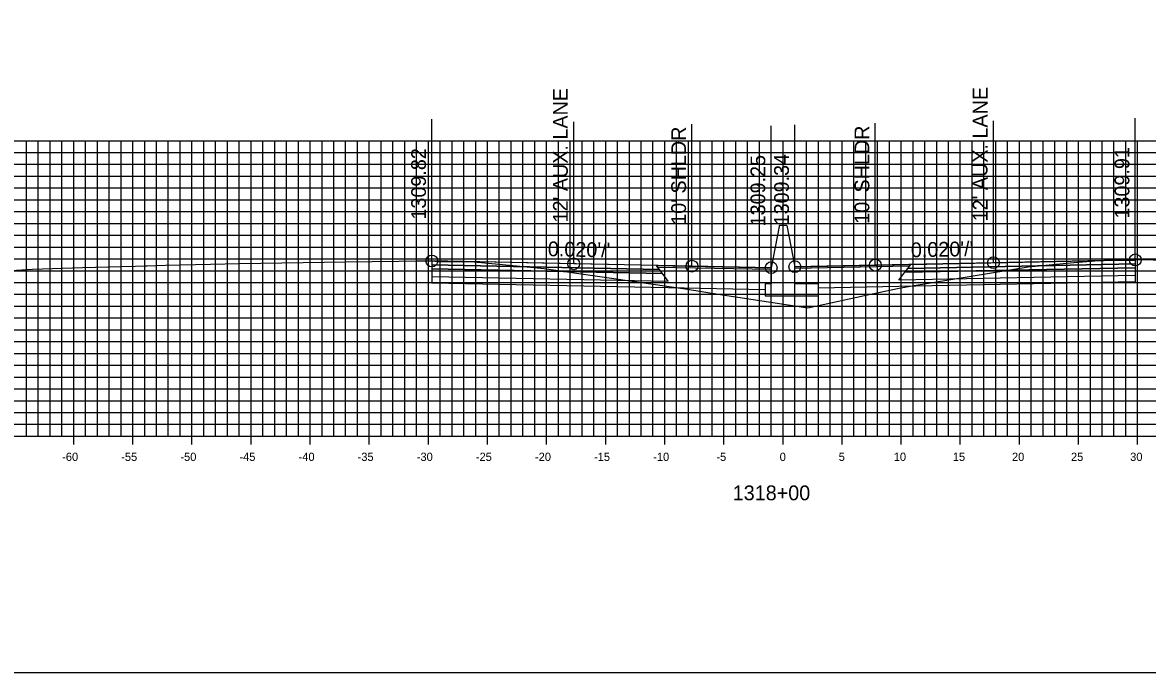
# Model space of a CAD drawing. Extents: x 674939 to 678919, y 750652 to 765176.
# Drawn here: x 678674.2 to 678769.4, y 751152.6 to 751207.6 of the extents above; entities that cross this region are included whole.
import ezdxf

# ---------------------------------------------------------------- set-up
doc = ezdxf.new("R2010")
doc.units = 0
for name, color, linetype in [('Level 10', 7, 'Continuous'), ('Level 17', 7, 'Continuous'), ('Level 18', 7, 'Continuous'), ('Level 19', 7, 'Continuous'), ('Level 20', 7, 'Continuous'), ('Level 22', 7, 'Continuous'), ('Level 23', 7, 'Continuous'), ('Level 4', 7, 'Continuous'), ('Level 8', 7, 'Continuous'), ('Level 9', 7, 'Continuous')]:
    doc.layers.add(name, color=color, linetype=linetype)

msp = doc.modelspace()

# ---------------------------------------------------------------- linework, layer by layer
at = {"layer": 'Level 10'}
msp.add_lwpolyline([(678672.798, 751186.531), (678675.035, 751186.674), (678679.285, 751186.811), (678682.538, 751186.906), (678683.76, 751186.937), (678684.6, 751186.959), (678684.754, 751186.963), (678686.303, 751187.004), (678690.088, 751187.095), (678692.56, 751187.145), (678701.524, 751187.286), (678706.033, 751187.361), (678707.563, 751187.382), (678708.483, 751187.391), (678708.729, 751187.38), (678708.827, 751187.374), (678709.304, 751187.338), (678709.738, 751187.319), (678710.774, 751187.315), (678711.453, 751187.312), (678711.708, 751187.314), (678712.399, 751187.288), (678712.653, 751187.271), (678712.689, 751187.269), (678712.719, 751187.267), (678715.986, 751186.956), (678718.318, 751186.739), (678727.154, 751185.464), (678730.457, 751184.993), (678733.041, 751184.565), (678740.643, 751183.41), (678746.07, 751184.596), (678748.361, 751185.085), (678749.462, 751185.263), (678759.271, 751186.884), (678762.815, 751187.201), (678764.57, 751187.358), (678764.635, 751187.365), (678765.181, 751187.419), (678765.69, 751187.423), (678766.053, 751187.428), (678766.902, 751187.437), (678768.09, 751187.446), (678768.181, 751187.446), (678768.232, 751187.452), (678768.336, 751187.463), (678768.346, 751187.465), (678768.581, 751187.49), (678774.86, 751187.367)], dxfattribs=at)
at = {"layer": 'Level 17'}
for points in [[(678738.203, 751190.299), (678737.533, 751186.799)], [(678738.863, 751190.387), (678738.863, 751190.387), (678738.203, 751190.387), (678738.203, 751190.299)], [(678738.863, 751190.387), (678739.533, 751186.887)], [(678737.533, 751186.799), (678737.533, 751185.424), (678737.033, 751185.424), (678737.033, 751184.424), (678741.533, 751184.424), (678741.533, 751185.424), (678739.533, 751185.424), (678739.533, 751186.887)]]:
    msp.add_lwpolyline(points, dxfattribs=at)
at = {"layer": 'Level 18'}
for points in [[(678768.336, 751187.463), (678756.336, 751187.223), (678746.336, 751187.023), (678739.533, 751186.887)], [(678737.533, 751186.799), (678730.827, 751186.934), (678720.827, 751187.134), (678708.827, 751187.374)]]:
    msp.add_lwpolyline(points, dxfattribs=at)
for points in [[(678768.336, 751187.463), (678768.336, 751187.133), (678749.086, 751186.748), (678749.336, 751187.083)], [(678708.827, 751187.374), (678708.827, 751187.044), (678728.077, 751186.659), (678727.827, 751186.994)], [(678727.827, 751186.994), (678737.533, 751186.799), (678737.537, 751186.642), (678727.947, 751186.834)], [(678749.217, 751186.924), (678739.533, 751186.73), (678739.533, 751186.887), (678749.336, 751187.083)]]:
    msp.add_lwpolyline(points, close=True, dxfattribs=at)
at = {"layer": 'Level 19'}
for points in [[(678708.827, 751187.044), (678708.827, 751186.714), (678728.327, 751186.324), (678728.077, 751186.659)], [(678708.827, 751186.714), (678708.827, 751186.054), (678728.827, 751185.654), (678728.327, 751186.324)], [(678768.336, 751186.803), (678768.336, 751186.143), (678748.336, 751185.743), (678748.836, 751186.413)], [(678768.336, 751187.133), (678768.336, 751186.803), (678748.836, 751186.413), (678749.086, 751186.748)]]:
    msp.add_lwpolyline(points, close=True, dxfattribs=at)
for points in [[(678708.827, 751186.054), (678708.827, 751185.514), (678728.827, 751185.114), (678737.033, 751184.949)], [(678768.336, 751186.143), (678768.336, 751185.603), (678748.336, 751185.203), (678741.533, 751185.067)]]:
    msp.add_lwpolyline(points, dxfattribs=at)
at = {"layer": 'Level 20'}
for p, q in [((678638.533, 751197.551), (678838.533, 751197.551)), ((678674.533, 751172.551), (678674.533, 751197.551)), ((678675.533, 751172.551), (678675.533, 751197.551)), ((678676.533, 751172.551), (678676.533, 751197.551)), ((678677.533, 751172.551), (678677.533, 751197.551)), ((678678.533, 751172.551), (678678.533, 751197.551)), ((678679.533, 751172.551), (678679.533, 751197.551)), ((678680.533, 751172.551), (678680.533, 751197.551)), ((678681.533, 751172.551), (678681.533, 751197.551)), ((678682.533, 751172.551), (678682.533, 751197.551)), ((678683.533, 751172.551), (678683.533, 751197.551)), ((678684.533, 751172.551), (678684.533, 751197.551)), ((678685.533, 751172.551), (678685.533, 751197.551)), ((678686.533, 751172.551), (678686.533, 751197.551)), ((678687.533, 751172.551), (678687.533, 751197.551)), ((678688.533, 751172.551), (678688.533, 751197.551)), ((678689.533, 751172.551), (678689.533, 751197.551)), ((678690.533, 751172.551), (678690.533, 751197.551)), ((678691.533, 751172.551), (678691.533, 751197.551)), ((678692.533, 751172.551), (678692.533, 751197.551)), ((678693.533, 751172.551), (678693.533, 751197.551)), ((678694.533, 751172.551), (678694.533, 751197.551)), ((678695.533, 751172.551), (678695.533, 751197.551)), ((678696.533, 751172.551), (678696.533, 751197.551)), ((678697.533, 751172.551), (678697.533, 751197.551)), ((678698.533, 751172.551), (678698.533, 751197.551)), ((678699.533, 751172.551), (678699.533, 751197.551)), ((678700.533, 751172.551), (678700.533, 751197.551)), ((678701.533, 751172.551), (678701.533, 751197.551)), ((678702.533, 751172.551), (678702.533, 751197.551)), ((678703.533, 751172.551), (678703.533, 751197.551)), ((678704.533, 751172.551), (678704.533, 751197.551)), ((678705.533, 751172.551), (678705.533, 751197.551)), ((678706.533, 751172.551), (678706.533, 751197.551)), ((678707.533, 751172.551), (678707.533, 751197.551)), ((678708.533, 751172.551), (678708.533, 751197.551)), ((678709.533, 751172.551), (678709.533, 751197.551)), ((678710.533, 751172.551), (678710.533, 751197.551)), ((678711.533, 751172.551), (678711.533, 751197.551)), ((678712.533, 751172.551), (678712.533, 751197.551)), ((678713.533, 751172.551), (678713.533, 751197.551)), ((678714.533, 751172.551), (678714.533, 751197.551)), ((678715.533, 751172.551), (678715.533, 751197.551)), ((678716.533, 751172.551), (678716.533, 751197.551)), ((678717.533, 751172.551), (678717.533, 751197.551)), ((678718.533, 751172.551), (678718.533, 751197.551)), ((678719.533, 751172.551), (678719.533, 751197.551)), ((678720.533, 751172.551), (678720.533, 751197.551)), ((678721.533, 751172.551), (678721.533, 751197.551)), ((678722.533, 751172.551), (678722.533, 751197.551)), ((678723.533, 751172.551), (678723.533, 751197.551)), ((678724.533, 751172.551), (678724.533, 751197.551)), ((678725.533, 751172.551), (678725.533, 751197.551)), ((678726.533, 751172.551), (678726.533, 751197.551)), ((678727.533, 751172.551), (678727.533, 751197.551)), ((678728.533, 751172.551), (678728.533, 751197.551)), ((678729.533, 751172.551), (678729.533, 751197.551)), ((678730.533, 751172.551), (678730.533, 751197.551)), ((678731.533, 751172.551), (678731.533, 751197.551)), ((678732.533, 751172.551), (678732.533, 751197.551)), ((678733.533, 751172.551), (678733.533, 751197.551)), ((678734.533, 751172.551), (678734.533, 751197.551)), ((678735.533, 751172.551), (678735.533, 751197.551)), ((678736.533, 751172.551), (678736.533, 751197.551)), ((678737.533, 751172.551), (678737.533, 751197.551)), ((678738.533, 751172.551), (678738.533, 751197.551)), ((678739.533, 751172.551), (678739.533, 751197.551)), ((678740.533, 751172.551), (678740.533, 751197.551)), ((678741.533, 751172.551), (678741.533, 751197.551)), ((678742.533, 751172.551), (678742.533, 751197.551)), ((678743.533, 751172.551), (678743.533, 751197.551)), ((678744.533, 751172.551), (678744.533, 751197.551)), ((678745.533, 751172.551), (678745.533, 751197.551)), ((678746.533, 751172.551), (678746.533, 751197.551)), ((678747.533, 751172.551), (678747.533, 751197.551)), ((678748.533, 751172.551), (678748.533, 751197.551)), ((678749.533, 751172.551), (678749.533, 751197.551)), ((678750.533, 751172.551), (678750.533, 751197.551)), ((678751.533, 751172.551), (678751.533, 751197.551)), ((678752.533, 751172.551), (678752.533, 751197.551)), ((678753.533, 751172.551), (678753.533, 751197.551)), ((678754.533, 751172.551), (678754.533, 751197.551)), ((678755.533, 751172.551), (678755.533, 751197.551)), ((678756.533, 751172.551), (678756.533, 751197.551)), ((678757.533, 751172.551), (678757.533, 751197.551)), ((678758.533, 751172.551), (678758.533, 751197.551)), ((678759.533, 751172.551), (678759.533, 751197.551)), ((678760.533, 751172.551), (678760.533, 751197.551)), ((678761.533, 751172.551), (678761.533, 751197.551)), ((678762.533, 751172.551), (678762.533, 751197.551)), ((678763.533, 751172.551), (678763.533, 751197.551)), ((678764.533, 751172.551), (678764.533, 751197.551)), ((678765.533, 751172.551), (678765.533, 751197.551)), ((678766.533, 751172.551), (678766.533, 751197.551)), ((678767.533, 751172.551), (678767.533, 751197.551)), ((678768.533, 751172.551), (678768.533, 751197.551)), ((678638.533, 751196.551), (678838.533, 751196.551)), ((678638.533, 751195.551), (678838.533, 751195.551)), ((678638.533, 751194.551), (678838.533, 751194.551)), ((678638.533, 751193.551), (678838.533, 751193.551)), ((678638.533, 751192.551), (678838.533, 751192.551)), ((678638.533, 751191.551), (678838.533, 751191.551)), ((678638.533, 751190.551), (678838.533, 751190.551)), ((678638.533, 751189.551), (678838.533, 751189.551)), ((678638.533, 751188.551), (678838.533, 751188.551)), ((678638.533, 751187.551), (678838.533, 751187.551)), ((678638.533, 751186.551), (678838.533, 751186.551)), ((678638.533, 751185.551), (678838.533, 751185.551)), ((678638.533, 751184.551), (678838.533, 751184.551)), ((678638.533, 751183.551), (678838.533, 751183.551)), ((678638.533, 751182.551), (678838.533, 751182.551)), ((678638.533, 751181.551), (678838.533, 751181.551)), ((678638.533, 751180.551), (678838.533, 751180.551)), ((678638.533, 751179.551), (678838.533, 751179.551)), ((678638.533, 751178.551), (678838.533, 751178.551)), ((678638.533, 751177.551), (678838.533, 751177.551)), ((678638.533, 751176.551), (678838.533, 751176.551)), ((678638.533, 751175.551), (678838.533, 751175.551)), ((678638.533, 751174.551), (678838.533, 751174.551)), ((678638.533, 751173.551), (678838.533, 751173.551)), ((678638.533, 751172.551), (678838.533, 751172.551))]:
    msp.add_line(p, q, dxfattribs=at)
at = {"layer": 'Level 23'}
for p, q in [((678708.827, 751187.374), (678708.827, 751199.374)), ((678720.827, 751187.134), (678720.827, 751199.134)), ((678730.827, 751186.934), (678730.827, 751198.934)), ((678739.533, 751186.887), (678739.533, 751198.887)), ((678746.336, 751187.023), (678746.336, 751199.023)), ((678756.336, 751187.223), (678756.336, 751199.223)), ((678768.336, 751187.463), (678768.336, 751199.463)), ((678737.533, 751186.799), (678737.533, 751198.799))]:
    msp.add_line(p, q, dxfattribs=at)
at = {"layer": 'Level 4'}
msp.add_lwpolyline([(678578.533, 751152.551), (678918.533, 751152.551), (678918.533, 751372.551), (678578.533, 751372.551)], close=True, dxfattribs=at)
for centre in [(678708.827, 751187.374), (678720.827, 751187.134), (678730.827, 751186.934), (678746.336, 751187.023), (678756.336, 751187.223), (678768.336, 751187.463), (678737.533, 751186.799), (678739.533, 751186.887)]:
    msp.add_circle(centre, 0.5, dxfattribs=at)
at = {"layer": 'Level 8'}
for p, q in [((678678.533, 751171.851), (678678.533, 751173.251)), ((678683.533, 751171.851), (678683.533, 751173.251)), ((678688.533, 751171.851), (678688.533, 751173.251)), ((678693.533, 751171.851), (678693.533, 751173.251)), ((678698.533, 751171.851), (678698.533, 751173.251)), ((678703.533, 751171.851), (678703.533, 751173.251)), ((678708.533, 751171.851), (678708.533, 751173.251)), ((678713.533, 751171.851), (678713.533, 751173.251)), ((678718.533, 751171.851), (678718.533, 751173.251)), ((678723.533, 751171.851), (678723.533, 751173.251)), ((678728.533, 751171.851), (678728.533, 751173.251)), ((678733.533, 751171.851), (678733.533, 751173.251)), ((678738.533, 751171.851), (678738.533, 751173.251)), ((678743.533, 751171.851), (678743.533, 751173.251)), ((678748.533, 751171.851), (678748.533, 751173.251)), ((678753.533, 751171.851), (678753.533, 751173.251)), ((678758.533, 751171.851), (678758.533, 751173.251)), ((678763.533, 751171.851), (678763.533, 751173.251)), ((678768.533, 751171.851), (678768.533, 751173.251)), ((678638.533, 751172.551), (678838.533, 751172.551))]:
    msp.add_line(p, q, dxfattribs=at)

# ---------------------------------------------------------------- texts
at = {"layer": 'Level 22'}
for rotation, p in [(358.85424, (678718.63, 751187.778)), (1.14576, (678749.361, 751187.684))]:
    msp.add_text("0.020'/'", height=1.25, rotation=rotation, dxfattribs=at).set_placement(p)
at = {"layer": 'Level 23'}
for s, p in [("12' AUX. LANE", (678720.327, 751190.634)), ("12' AUX. LANE", (678755.836, 751190.723)), ("10' SHLDR", (678730.327, 751190.434)), ("10' SHLDR", (678745.836, 751190.523)), ('1309.91', (678767.836, 751190.963)), ('1309.82', (678708.327, 751190.874)), ('1309.25', (678737.033, 751190.299)), ('1309.34', (678739.033, 751190.387))]:
    msp.add_text(s, height=1.25, rotation=90, dxfattribs=at).set_placement(p)
at = {"layer": 'Level 9'}
for s, height, p in [('-60', 0.7, (678677.552, 751170.451)), ('-55', 0.7, (678682.546, 751170.451)), ('-50', 0.7, (678687.552, 751170.451)), ('-45', 0.7, (678692.546, 751170.451)), ('-40', 0.7, (678697.552, 751170.451)), ('-35', 0.7, (678702.546, 751170.451)), ('-30', 0.7, (678707.552, 751170.451)), ('-25', 0.7, (678712.546, 751170.451)), ('-20', 0.7, (678717.552, 751170.451)), ('-15', 0.7, (678722.546, 751170.451)), ('-10', 0.7, (678727.552, 751170.451)), ('-5', 0.7, (678732.896, 751170.451)), ('0', 0.7, (678738.252, 751170.451)), ('5', 0.7, (678743.246, 751170.451)), ('10', 0.7, (678747.902, 751170.451)), ('15', 0.7, (678752.896, 751170.451)), ('20', 0.7, (678757.902, 751170.451)), ('25', 0.7, (678762.896, 751170.451)), ('30', 0.7, (678767.902, 751170.451)), ('1318+00', 1.25, (678734.281, 751167.126))]:
    msp.add_text(s, height=height, dxfattribs=at).set_placement(p)

doc.saveas('drawing.dxf')
